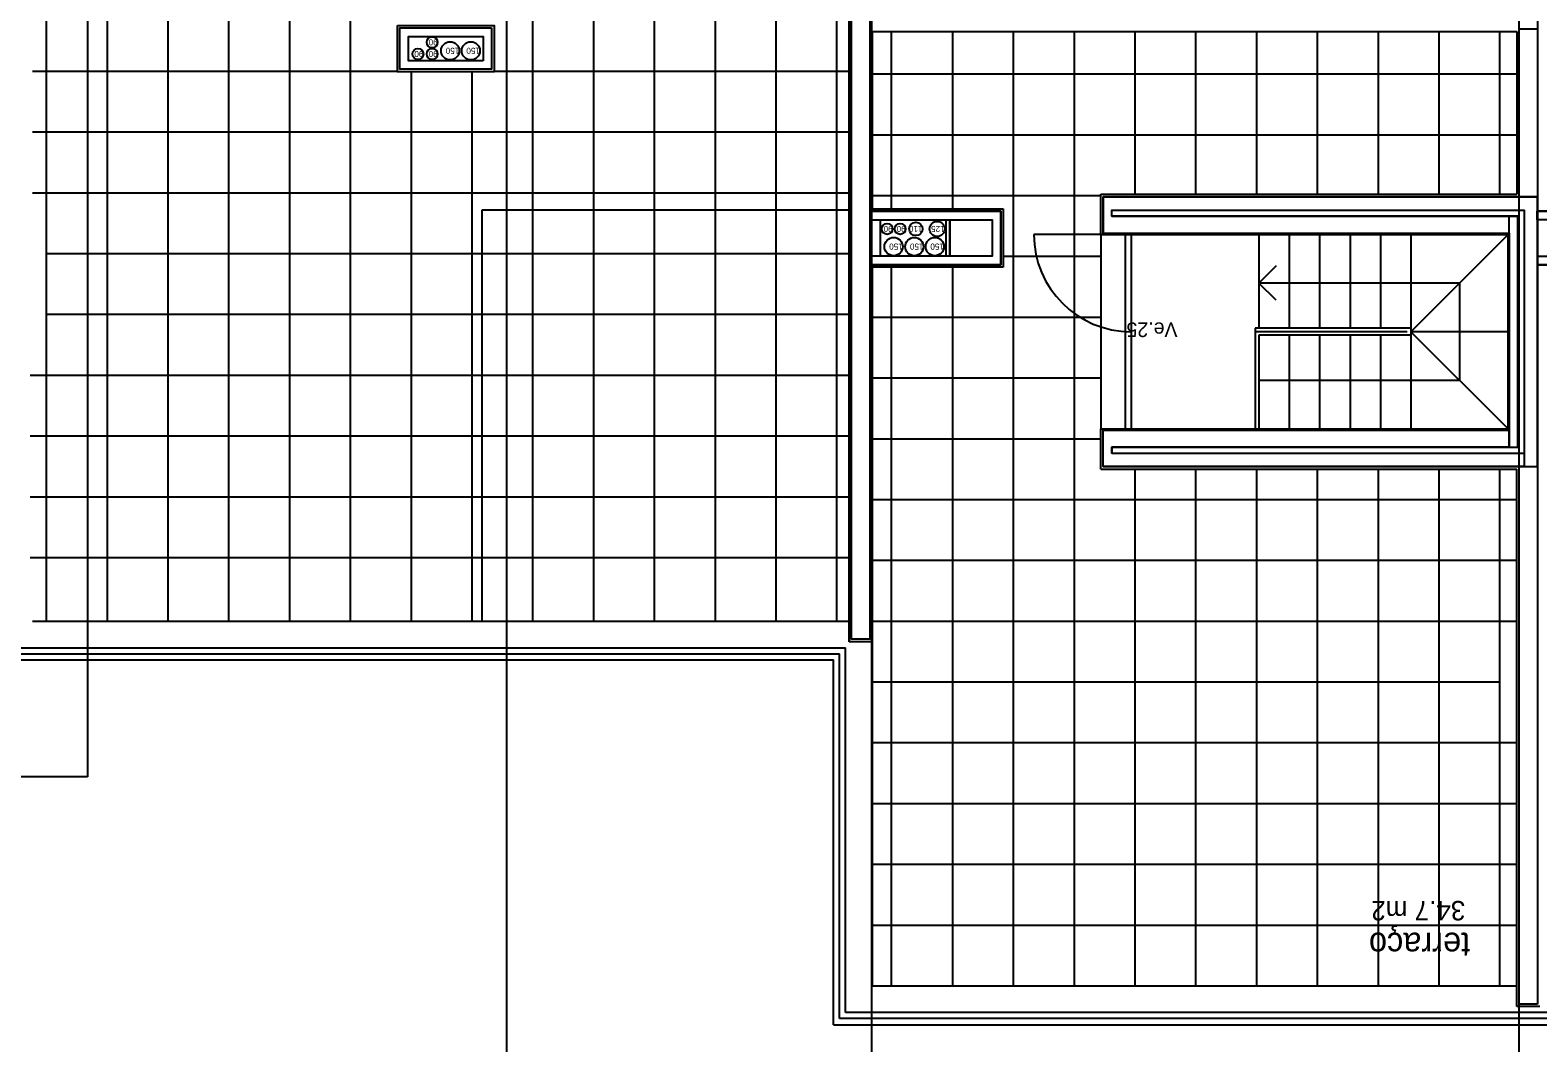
# Model space of a CAD drawing. Extents: x 1278 to 1356, y -253.7 to -224.
# Drawn here: x 1311.64 to 1324.04, y -247.07 to -238.74 of the extents above; entities that cross this region are included whole.
import ezdxf

# ---------------------------------------------------------------- set-up
doc = ezdxf.new("R2010")
doc.units = 0
for name, color, linetype in [('corte', 7, 'Continuous'), ('estereoctomias', 7, 'Continuous'), ('estrutura-eixos', 7, 'Continuous'), ('Level 1', 7, 'Continuous'), ('Level 13', 7, 'Continuous'), ('Level 2', 7, 'Continuous'), ('Level 21', 7, 'Continuous'), ('Level 40', 7, 'Continuous'), ('Level 41', 7, 'Continuous'), ('Level 59', 7, 'Continuous'), ('Level 60', 7, 'Continuous'), ('revestimentos', 7, 'Continuous'), ('vista', 7, 'Continuous')]:
    doc.layers.add(name, color=color, linetype=linetype)

msp = doc.modelspace()

# ---------------------------------------------------------------- linework, layer by layer
at = {"layer": 'corte'}
for p, q in [((1315.353, -240.224), (1315.353, -243.604)), ((1318.374, -240.224), (1315.353, -240.224)), ((1318.544, -240.234), (1319.621, -240.234)), ((1318.544, -240.304), (1319.551, -240.304)), ((1319.171, -240.604), (1319.171, -240.304)), ((1319.201, -240.604), (1319.201, -240.304)), ((1319.551, -240.304), (1319.551, -240.604)), ((1319.621, -240.234), (1319.621, -240.674)), ((1320.533, -240.224), (1323.924, -240.224)), ((1320.533, -240.274), (1320.533, -240.224)), ((1320.533, -240.274), (1323.874, -240.274)), ((1323.874, -240.274), (1323.874, -242.174)), ((1323.924, -240.224), (1323.924, -242.224)), ((1324.952, -240.304), (1324.032, -240.304)), ((1325.022, -240.234), (1324.034, -240.234)), ((1319.551, -240.604), (1318.544, -240.604)), ((1319.621, -240.674), (1318.544, -240.674)), ((1324.032, -240.604), (1324.952, -240.604)), ((1324.034, -240.674), (1325.022, -240.674))]:
    msp.add_line(p, q, dxfattribs=at)
for points in [[(1315.433, -238.726), (1315.433, -239.066), (1314.679, -239.066), (1314.679, -238.726)], [(1315.363, -238.996), (1314.749, -238.996), (1314.749, -238.796), (1315.363, -238.796)]]:
    msp.add_lwpolyline(points, close=True, dxfattribs=at)
at = {"layer": 'estereoctomias'}
for p, q in [((1318.723, -240.214), (1318.723, -238.754)), ((1318.723, -246.604), (1318.723, -240.694))]:
    msp.add_line(p, q, dxfattribs=at)
for points in [[(1318.394, -232.094), (1318.544, -232.094), (1318.544, -243.754), (1318.394, -243.754), (1318.394, -237.106), (1318.434, -237.106), (1318.434, -235.084), (1318.394, -235.084)], [(1324.034, -240.114), (1323.884, -240.114), (1323.884, -238.734), (1324.034, -238.734)], [(1324.034, -240.114), (1320.463, -240.114), (1320.463, -240.414), (1323.803, -240.414), (1323.803, -242.174), (1323.874, -242.174), (1323.874, -240.414), (1323.874, -240.284), (1323.874, -240.274), (1320.533, -240.274), (1320.533, -240.224), (1323.924, -240.224), (1323.924, -242.334), (1324.034, -242.334), (1324.034, -240.224)], [(1318.544, -240.674), (1319.621, -240.674), (1319.621, -240.234), (1318.544, -240.234), (1318.544, -240.304), (1319.551, -240.304), (1319.551, -240.604), (1318.544, -240.604)], [(1319.201, -240.604), (1319.171, -240.604), (1319.171, -240.304), (1319.201, -240.304)], [(1325.022, -240.674), (1324.034, -240.674), (1324.034, -240.604), (1324.952, -240.604), (1324.952, -240.304), (1324.032, -240.304), (1324.032, -240.234), (1325.022, -240.234)], [(1323.924, -242.224), (1323.924, -242.334), (1320.463, -242.334), (1320.463, -242.034), (1323.803, -242.034), (1323.803, -242.174), (1320.533, -242.174), (1320.533, -242.224)], [(1324.034, -246.754), (1323.884, -246.754), (1323.884, -242.334), (1324.034, -242.334)]]:
    msp.add_lwpolyline(points, close=True, dxfattribs=at)
at = {"layer": 'estrutura-eixos'}
for p, q in [((1315.559, -250.792), (1315.559, -229.62)), ((1318.559, -250.792), (1318.559, -229.62)), ((1323.884, -250.792), (1323.884, -229.62))]:
    msp.add_line(p, q, dxfattribs=at)
at = {"layer": 'Level 1'}
for p, q in [((1318.544, -232.094), (1318.544, -243.754)), ((1324.034, -232.094), (1324.034, -246.754)), ((1318.394, -243.754), (1318.394, -237.106)), ((1323.884, -240.114), (1323.884, -238.734)), ((1320.463, -240.114), (1324.034, -240.114)), ((1320.463, -240.414), (1320.463, -240.114)), ((1323.803, -242.174), (1323.803, -240.274)), ((1320.463, -240.414), (1323.803, -240.414)), ((1320.463, -242.034), (1323.803, -242.034)), ((1320.463, -242.334), (1320.463, -242.034)), ((1320.533, -242.174), (1323.874, -242.174)), ((1320.533, -242.224), (1320.533, -242.174)), ((1320.533, -242.224), (1323.924, -242.224)), ((1320.463, -242.334), (1324.034, -242.334)), ((1323.884, -246.754), (1323.884, -242.334)), ((1318.544, -243.754), (1318.394, -243.754)), ((1324.034, -246.754), (1323.884, -246.754))]:
    msp.add_line(p, q, dxfattribs=at)
at = {"layer": 'Level 13'}
for p, q in [((1320.643, -240.424), (1319.893, -240.424)), ((1320.643, -240.424), (1320.643, -242.024)), ((1320.693, -240.424), (1320.693, -242.024))]:
    msp.add_line(p, q, dxfattribs=at)
msp.add_arc((1320.693, -240.424), 0.8, 180, 270, dxfattribs=at)
at = {"layer": 'Level 2'}
for p, q in [((1320.443, -240.424), (1320.443, -242.024)), ((1321.743, -240.424), (1321.743, -241.194)), ((1321.993, -240.424), (1321.993, -241.194)), ((1322.243, -240.424), (1322.243, -241.194)), ((1322.493, -240.424), (1322.493, -241.194)), ((1322.743, -240.424), (1322.743, -241.194)), ((1322.993, -240.424), (1322.993, -241.194)), ((1322.993, -241.224), (1323.793, -240.424)), ((1321.885, -240.683), (1321.743, -240.824)), ((1323.393, -240.824), (1321.743, -240.824)), ((1321.885, -240.965), (1321.743, -240.824)), ((1323.393, -240.824), (1323.393, -241.624)), ((1322.993, -241.194), (1321.713, -241.194)), ((1321.713, -241.194), (1321.713, -242.024)), ((1322.962, -241.224), (1321.713, -241.224)), ((1322.993, -241.254), (1321.743, -241.254)), ((1321.743, -241.254), (1321.743, -242.024)), ((1321.743, -241.254), (1321.743, -242.024)), ((1321.993, -241.254), (1321.993, -242.024)), ((1322.243, -241.254), (1322.243, -242.024)), ((1322.493, -241.254), (1322.493, -242.024)), ((1322.743, -241.254), (1322.743, -242.024)), ((1322.993, -241.194), (1322.993, -241.254)), ((1323.793, -241.224), (1322.993, -241.224)), ((1322.993, -241.224), (1323.793, -242.024)), ((1322.993, -241.254), (1322.993, -242.024)), ((1321.743, -241.624), (1323.393, -241.624)), ((1311.658, -243.604), (1318.374, -243.604)), ((1299.193, -243.824), (1318.344, -243.824)), ((1299.193, -243.874), (1318.294, -243.874)), ((1318.294, -246.874), (1318.294, -243.874)), ((1318.294, -246.874), (1318.294, -243.874)), ((1318.344, -246.824), (1318.344, -243.824)), ((1318.344, -246.824), (1318.344, -243.824)), ((1299.193, -243.924), (1318.244, -243.924)), ((1318.244, -246.924), (1318.244, -243.924)), ((1318.244, -246.924), (1318.244, -243.924)), ((1318.564, -246.604), (1323.864, -246.604)), ((1323.943, -246.874), (1318.294, -246.874)), ((1323.943, -246.824), (1318.344, -246.824)), ((1345.543, -246.824), (1323.919, -246.824)), ((1345.543, -246.874), (1323.919, -246.874)), ((1318.244, -246.924), (1323.943, -246.924)), ((1323.943, -246.924), (1345.543, -246.924))]:
    msp.add_line(p, q, dxfattribs=at)
at = {"layer": 'Level 21'}
for p, q in [((1311.773, -243.604), (1311.773, -232.244)), ((1312.273, -243.604), (1312.273, -232.244)), ((1312.773, -243.604), (1312.773, -237.126)), ((1313.273, -243.604), (1313.273, -237.126)), ((1313.773, -243.604), (1313.773, -237.126)), ((1314.273, -243.604), (1314.273, -237.126)), ((1315.773, -243.604), (1315.773, -237.126)), ((1316.273, -243.604), (1316.273, -237.126)), ((1316.773, -243.604), (1316.773, -237.126)), ((1317.273, -243.604), (1317.273, -237.126)), ((1317.773, -243.604), (1317.773, -237.126)), ((1318.273, -243.604), (1318.273, -237.126)), ((1319.223, -238.754), (1319.223, -240.214)), ((1319.723, -238.754), (1319.723, -246.604)), ((1320.223, -238.754), (1320.223, -246.604)), ((1320.723, -238.754), (1320.723, -240.094)), ((1321.223, -238.754), (1321.223, -240.094)), ((1321.723, -238.754), (1321.723, -240.094)), ((1322.223, -238.754), (1322.223, -240.094)), ((1322.723, -238.754), (1322.723, -240.094)), ((1323.223, -238.754), (1323.223, -240.094)), ((1323.723, -238.754), (1323.723, -240.094)), ((1314.659, -239.084), (1311.658, -239.084)), ((1314.773, -243.604), (1314.773, -239.086)), ((1315.273, -243.604), (1315.273, -239.086)), ((1318.374, -239.084), (1315.453, -239.084)), ((1318.564, -239.104), (1323.864, -239.104)), ((1318.374, -239.584), (1311.658, -239.584)), ((1318.564, -239.604), (1323.864, -239.604)), ((1318.374, -240.084), (1311.658, -240.084)), ((1318.564, -240.104), (1320.443, -240.104)), ((1318.374, -240.584), (1311.773, -240.584)), ((1319.641, -240.604), (1320.443, -240.604)), ((1319.223, -240.694), (1319.223, -246.604)), ((1318.374, -241.084), (1311.773, -241.084)), ((1318.564, -241.104), (1320.443, -241.104)), ((1318.374, -241.584), (1311.638, -241.584)), ((1318.564, -241.604), (1320.443, -241.604)), ((1318.374, -242.084), (1311.638, -242.084)), ((1318.564, -242.104), (1320.443, -242.104)), ((1320.723, -242.354), (1320.723, -246.604)), ((1321.223, -242.354), (1321.223, -246.604)), ((1321.723, -242.354), (1321.723, -246.604)), ((1322.223, -242.354), (1322.223, -246.604)), ((1322.723, -242.354), (1322.723, -246.604)), ((1323.223, -242.354), (1323.223, -246.604)), ((1323.723, -242.354), (1323.723, -246.604)), ((1318.374, -242.584), (1311.638, -242.584)), ((1318.564, -242.604), (1323.864, -242.604)), ((1318.374, -243.084), (1311.638, -243.084)), ((1318.564, -243.104), (1323.864, -243.104)), ((1318.564, -243.604), (1323.864, -243.604)), ((1318.564, -244.104), (1323.723, -244.104)), ((1318.564, -244.604), (1323.864, -244.604)), ((1318.564, -245.104), (1323.864, -245.104)), ((1318.564, -245.604), (1323.864, -245.604)), ((1318.564, -246.104), (1323.864, -246.104))]:
    msp.add_line(p, q, dxfattribs=at)
at = {"layer": 'Level 41'}
for centre, radius in [((1314.944, -238.844), 0.045), ((1314.827, -238.94), 0.045), ((1314.944, -238.94), 0.045), ((1315.092, -238.914), 0.075), ((1315.262, -238.914), 0.075), ((1318.686, -240.379), 0.045), ((1318.793, -240.379), 0.045), ((1318.922, -240.379), 0.055), ((1319.097, -240.379), 0.0625), ((1318.739, -240.524), 0.075), ((1318.91, -240.524), 0.075), ((1319.078, -240.524), 0.075)]:
    msp.add_circle(centre, radius, dxfattribs=at)
at = {"layer": 'Level 59'}
msp.add_lwpolyline([(1312.108, -244.886), (1306.965, -244.886), (1306.965, -231.008), (1312.108, -231.008)], close=True, dxfattribs=at)
at = {"layer": 'revestimentos'}
for p, q in [((1318.374, -237.126), (1318.374, -243.774)), ((1318.374, -243.774), (1318.374, -237.254)), ((1318.564, -238.754), (1323.864, -238.754)), ((1318.564, -238.754), (1318.564, -240.214)), ((1323.864, -238.754), (1323.864, -240.094)), ((1320.443, -240.424), (1320.443, -240.094)), ((1320.443, -240.094), (1323.864, -240.094)), ((1318.564, -240.214), (1319.641, -240.214)), ((1319.641, -240.214), (1319.641, -240.694)), ((1320.443, -240.424), (1323.793, -240.424)), ((1323.793, -242.024), (1323.793, -240.424)), ((1319.641, -240.694), (1318.564, -240.694)), ((1318.564, -240.694), (1318.564, -243.774)), ((1320.443, -242.354), (1320.443, -242.024)), ((1320.443, -242.024), (1323.793, -242.024)), ((1320.443, -242.354), (1323.864, -242.354)), ((1323.864, -246.774), (1323.864, -242.354)), ((1318.564, -243.774), (1318.374, -243.774)), ((1324.054, -246.774), (1323.864, -246.774))]:
    msp.add_line(p, q, dxfattribs=at)
msp.add_lwpolyline([(1314.659, -238.706), (1315.453, -238.706), (1315.453, -239.086), (1314.659, -239.086)], close=True, dxfattribs=at)
at = {"layer": 'vista'}
for p, q in [((1318.631, -240.604), (1318.631, -240.304)), ((1318.564, -243.774), (1318.564, -246.604))]:
    msp.add_line(p, q, dxfattribs=at)

# ---------------------------------------------------------------- texts
at = {"layer": 'Level 40'}
msp.add_text('Ve.25', height=0.12, rotation=180, dxfattribs=at).set_placement((1321.074, -241.148))
at = {"layer": 'Level 41'}
for s, p in [('90', (1314.989, -238.819)), ('90', (1314.872, -238.915)), ('90', (1314.989, -238.915)), ('150', (1315.167, -238.889)), ('150', (1315.337, -238.889)), ('90', (1318.731, -240.354)), ('90', (1318.838, -240.354)), ('110', (1318.977, -240.354)), ('125', (1319.159, -240.354)), ('150', (1318.814, -240.499)), ('150', (1318.985, -240.499)), ('150', (1319.153, -240.499))]:
    msp.add_text(s, height=0.05, rotation=180, dxfattribs=at).set_placement(p)
at = {"layer": 'Level 60'}
for s, height, p in [('34.7 m2', 0.16, (1323.441, -245.906)), ('terraço', 0.2, (1323.481, -246.167))]:
    msp.add_text(s, height=height, rotation=180, dxfattribs=at).set_placement(p)

doc.saveas('drawing.dxf')
